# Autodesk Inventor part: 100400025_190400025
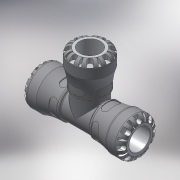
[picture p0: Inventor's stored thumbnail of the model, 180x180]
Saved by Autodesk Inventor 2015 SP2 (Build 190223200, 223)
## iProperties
Created: 2016-12
Part Number: 100400025_190400025
Material: Generic
Description: PLASSON TEE 25X25X25 SERIES 1
Document SubType Name: Modeling
Designer: KIM
Mass: 664.223 g
Surface Area: 733.008 cm^2
Volume: 474.445 cm^3
Density: 1 g/cm^3
Appearance: Default
Author: KIM
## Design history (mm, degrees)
derived "1004.ipt"
feature "Solid1::1004.ipt"
tag "TaggingFeature1"
body "Solid1"
other parameters: "d1" = 20.16, "d2" = 25, "d3" = 31.25, "d4" = 47, "d8" = 39.95, "d13" = 6.3, "d14" = 6.3, "d15" = 0, "d17" = 360 deg, "d19" = 8 deg, "d20" = 0.5, "d21" = 0.5, "d22" = 8 deg, "d24" = 0, "d26" = 360 deg, "d33" = 4.7, "d43" = 36.66, "d51" = 0.47, "d54" = 8.75, "d55" = 5.5, "d57" = 12.348, "d58" = 0, "d74" = 0, "d77" = 2.08333, "d78" = 48, "d79" = 36.66, "d80" = 134, "d82" = 0.5, "d115" = 360 deg, "d139" = 6.3, "d140" = 0, "d142" = 360 deg, "d207" = 90 deg, "d209" = 20.16, "d210" = 25, "d211" = 31.25, "d212" = 47, "d213" = 39.95, "d215" = 36.66, "d216" = 2.08333, "d217" = 48, "d225" = 78, "d226" = 48, "d228" = 7.4375, "d229" = 6.3, "d233" = 6.3, "d234" = 0, "d236" = 360 deg, "d238" = 8 deg, "d239" = 8 deg, "d240" = 0.5, "d241" = 0.5, "d243" = 0, "d245" = 360 deg, "d247" = 0.94, "d248" = 2.88, "d249" = 2.88, "d250" = 7.4375, "d252" = 8.75, "d253" = 5.75, "d254" = 12.348, "d255" = 0, "d257" = 360 deg, "d259" = 0.5, "d261" = 0, "d262" = 0.94, "d264" = 0, "d266" = 0, "d267" = 0.47, "d_" = 25, "E_" = 47, "l_" = 48, "A_" = 78, "H_" = 134, "d9" = 7.875, "d11" = 47, "d12" = 31.25, "d230" = 47, "d231" = 31.25, "d232" = 7.875
